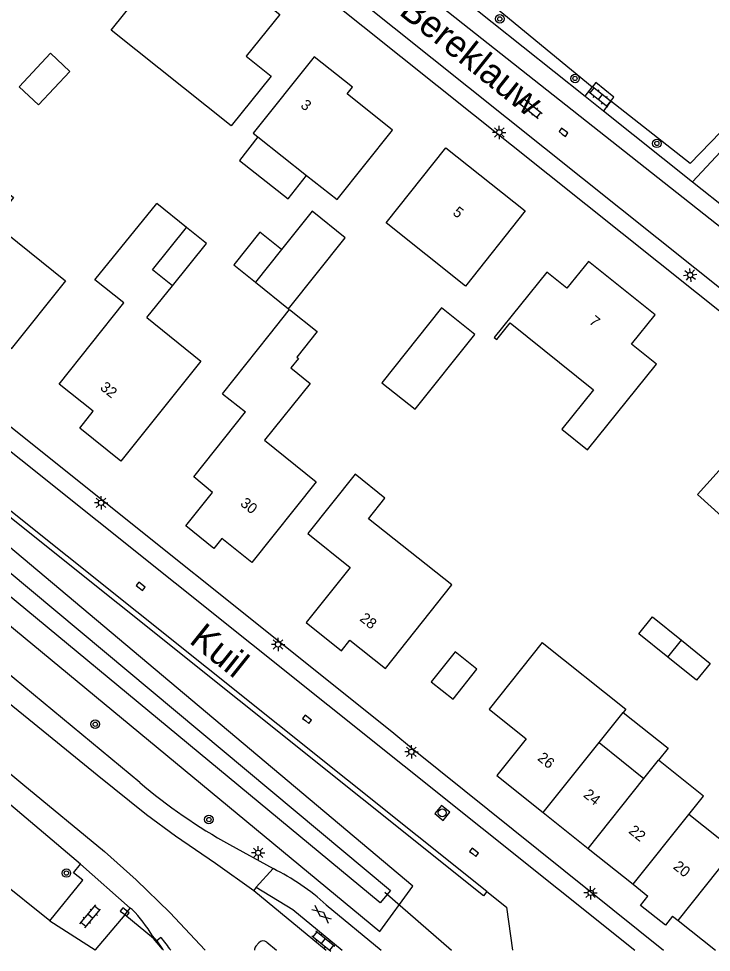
# Model space of a CAD drawing. Extents: x 136000 to 141014, y 402000 to 403500.
# Drawn here: x 137167.8 to 137232.8, y 401999.8 to 402087.3 of the extents above; entities that cross this region are included whole.
import ezdxf

# ---------------------------------------------------------------- set-up
doc = ezdxf.new("R2010")
doc.units = 0
for name, color, linetype in [('gg-anno-huisnummerreeks BGT', 7, 'Continuous'), ('gg-anno-openbare ruimte label', 7, 'Continuous'), ('gg-bbg-bijgebouw', 7, 'Continuous'), ('gg-bbg-gedigitaliseerde bebouwing', 7, 'Continuous'), ('gg-bbg-gedigitaliseerde bijgebouw', 7, 'Continuous'), ('gg-bbg-hoofdgebouw', 7, 'Continuous'), ('gg-bbg-luifel en loopbrug', 7, 'Continuous'), ('gg-bbg-tussenscheiding', 7, 'Continuous'), ('gg-knt-verharding', 7, 'Continuous'), ('gg-knt-verharding nz', 7, 'Continuous'), ('gg-kntw-bovenkant insteek waterloop', 7, 'Continuous'), ('gg-kntw-waterlijn', 7, 'Continuous'), ('gg-kwrk-duiker nz buis', 7, 'Continuous'), ('gt-grn-groengrens', 7, 'Continuous'), ('gt-grn-weggrens', 7, 'Continuous'), ('gt-symb-boom', 7, 'Continuous'), ('gt-symb-gesloten verharding', 7, 'Continuous'), ('gt-symb-klinker verharding', 7, 'Continuous'), ('gt-symb-kolk', 7, 'Continuous'), ('gt-symb-lichtmast', 7, 'Continuous'), ('gt-symb-rioolschacht', 7, 'Continuous')]:
    doc.layers.add(name, color=color, linetype=linetype)

# ---------------------------------------------------------------- blocks, each defined once
blk = doc.blocks.new('gt0-BOOM')
at = {"layer": 'gt-symb-boom'}
for radius in [0.4, 0.2]:
    blk.add_circle((0, 0), radius, dxfattribs=at)
blk = doc.blocks.new('gt0-KOLK')
at = {"layer": 'gt-symb-kolk'}
blk.add_lwpolyline([(0, 0), (0.375, 0), (0.375, 0.4), (-0.375, 0.4), (-0.375, 0), (0, 0)], dxfattribs=at)
blk = doc.blocks.new('gt0-LMAST')
at = {"layer": 'gt-symb-lichtmast'}
for p, q in [((-0.182, 0.173), (-0.447, 0.438)), ((-0.005, 0.246), (-0.005, 0.621)), ((0.172, 0.173), (0.437, 0.438)), ((-0.255, -0.004), (-0.63, -0.004)), ((-0.182, -0.181), (-0.447, -0.446)), ((-0.005, -0.254), (-0.005, -0.629)), ((0.437, -0.446), (0.172, -0.181)), ((0.245, -0.004), (0.62, -0.004))]:
    blk.add_line(p, q, dxfattribs=at)
blk.add_circle((-0.005, -0.004), 0.25, dxfattribs=at)
blk = doc.blocks.new('gt0-KL1')
at = {"layer": 'gt-symb-klinker verharding'}
for p, q in [((-1.15, 0.3), (1.15, 0.3)), ((-1, -0.3), (-1, 0.3)), ((-0.5, 0.3), (-0.5, 0.45)), ((0, -0.3), (0, 0.3)), ((0.5, 0.3), (0.5, 0.45)), ((1, -0.3), (1, 0.3)), ((-1.15, -0.3), (1.15, -0.3)), ((-0.5, -0.45), (-0.5, -0.3)), ((0.5, -0.45), (0.5, -0.3))]:
    blk.add_line(p, q, dxfattribs=at)
blk = doc.blocks.new('gt0-GESVH1')
at = {"layer": 'gt-symb-gesloten verharding'}
for p, q in [((-0.992, -0.261), (0.008, 0.239)), ((0.008, -0.261), (-0.992, 0.239)), ((0.008, 0.239), (1.008, -0.261)), ((1.008, 0.239), (0.008, -0.261))]:
    blk.add_line(p, q, dxfattribs=at)
blk = doc.blocks.new('gt0-RS')
at = {"layer": 'gt-symb-rioolschacht'}
blk.add_lwpolyline([(-0.5, -0.5), (0.5, -0.5), (0.5, 0.5), (-0.5, 0.5)], close=True, dxfattribs=at)
blk.add_circle((0, 0), 0.375, dxfattribs=at)

msp = doc.modelspace()

# ---------------------------------------------------------------- linework, layer by layer
at = {"layer": 'gg-bbg-bijgebouw'}
for points in [[(137193.142, 402060.138), (137198.47, 402066.8), (137195.35, 402069.29)], [(137210.63, 402057.74), (137207.5, 402060.24), (137201.89, 402053.21), (137205.01, 402050.72), (137210.63, 402057.74)]]:
    msp.add_lwpolyline(points, dxfattribs=at)
at = {"layer": 'gg-bbg-gedigitaliseerde bebouwing'}
for p, q in [((137183.596, 402067.758), (137180.79, 402070.02)), ((137179.85, 402059.31), (137182.259, 402062.297)), ((137186.96, 402052.18), (137191.33, 402057.66)), ((137222.269, 402019.477), (137224.534, 402022.3)), ((137222.269, 402019.477), (137226.474, 402016.113)), ((137226.474, 402016.113), (137227.848, 402017.832)), ((137234.901, 402009.371), (137230.69, 402012.74))]:
    msp.add_line(p, q, dxfattribs=at)
for points in [[(137182.259, 402062.297), (137180.4, 402063.795), (137183.596, 402067.758)], [(137191.33, 402057.66), (137193.242, 402060.058), (137195.83, 402057.995), (137193.924, 402055.605), (137194.08, 402055.48)], [(137194.08, 402055.48), (137193.369, 402054.598), (137195.183, 402053.134), (137190.887, 402047.806), (137195.73, 402043.9)], [(137238.45, 402050.46), (137231.492, 402042.741), (137236.657, 402038.085), (137235.581, 402036.891), (137238.621, 402034.15)], [(137216.94, 402028.85), (137224.766, 402022.589), (137224.534, 402022.3)], [(137230.69, 402012.74), (137232.064, 402014.458), (137227.848, 402017.832)]]:
    msp.add_lwpolyline(points, dxfattribs=at)
at = {"layer": 'gg-bbg-gedigitaliseerde bijgebouw'}
for p, q in [((137195.35, 402069.29), (137192.477, 402065.692)), ((137192.477, 402065.692), (137190.04, 402062.64)), ((137190.04, 402062.64), (137193.142, 402060.138))]:
    msp.add_line(p, q, dxfattribs=at)
for points in [[(137167.893, 402080.955), (137169.716, 402079.246), (137172.657, 402082.382), (137170.834, 402084.091), (137167.893, 402080.955)], [(137228.711, 402027.483), (137225.98, 402029.68), (137227.26, 402031.26), (137229.987, 402029.066)], [(137229.987, 402029.066), (137232.68, 402026.9), (137231.4, 402025.32), (137228.711, 402027.483)], [(137206.535, 402025.152), (137208.576, 402023.534), (137210.807, 402026.349), (137208.765, 402027.967), (137206.535, 402025.152)]]:
    msp.add_lwpolyline(points, dxfattribs=at)
at = {"layer": 'gg-bbg-hoofdgebouw'}
for p, q in [((137190.273, 402076.248), (137194.844, 402072.635)), ((137227.51, 402059.57), (137221.27, 402064.58)), ((137186.96, 402052.18), (137189.105, 402050.484)), ((137184.26, 402044.38), (137189.105, 402050.484)), ((137217.016, 402012.929), (137221.235, 402009.554)), ((137221.235, 402009.554), (137225.448, 402006.184)), ((137225.448, 402006.184), (137226.837, 402005.073)), ((137229.16, 402003.214), (137229.672, 402002.805)), ((137229.672, 402002.805), (137233.178, 402000))]:
    msp.add_line(p, q, dxfattribs=at)
for points in [[(137192.338, 402087.711), (137189.19, 402083.82), (137191.528, 402081.943), (137187.777, 402077.273), (137176.53, 402086.27), (137183.426, 402094.866), (137183.663, 402094.68), (137183.16, 402094.05), (137187.871, 402090.297), (137188.375, 402090.91), (137192.338, 402087.711)], [(137202.89, 402076.89), (137198.65, 402080.28), (137199.15, 402080.9), (137195.56, 402083.75), (137189.84, 402076.59), (137190.273, 402076.248)], [(137194.844, 402072.635), (137197.71, 402070.37), (137202.89, 402076.89)], [(137215.35, 402069.31), (137209.75, 402062.27), (137202.3, 402068.2), (137207.89, 402075.24), (137215.35, 402069.31)], [(137156.9, 402067.42), (137162.52, 402074.43), (137167.36, 402070.56), (137165.46, 402068.18), (137172.24, 402062.75), (137167.14, 402056.37), (137161.75, 402060.66), (137161.28, 402060.08), (137157.99, 402062.71), (137159.86, 402065.05), (137156.9, 402067.42)], [(137179.85, 402059.31), (137184.93, 402055.24), (137177.41, 402045.85), (137173.57, 402048.94), (137174.83, 402050.53), (137171.64, 402053.07), (137177.7, 402060.69), (137175, 402062.84), (137180.79, 402070.02)], [(137221.27, 402064.58), (137219.251, 402062.072), (137217.381, 402063.576), (137212.441, 402057.438), (137212.674, 402057.25), (137213.928, 402058.808), (137221.74, 402052.55)], [(137221.19, 402046.92), (137227.654, 402054.948), (137225.309, 402056.836), (137227.51, 402059.57)], [(137221.74, 402052.55), (137218.781, 402048.864), (137221.19, 402046.92)], [(137195.73, 402043.9), (137189.72, 402036.36), (137186.89, 402038.61), (137186.14, 402037.68), (137183.51, 402039.79), (137186.02, 402042.93), (137184.26, 402044.38)], [(137208.47, 402034.25), (137200.65, 402040.45), (137202.19, 402042.37), (137199.38, 402044.63), (137194.97, 402039.06), (137198.92, 402035.9), (137194.79, 402030.73), (137198.11, 402028.08), (137198.91, 402029.08), (137202.23, 402026.41), (137208.47, 402034.25)], [(137216.94, 402028.85), (137211.95, 402022.62), (137215.44, 402019.83), (137212.69, 402016.39), (137217.016, 402012.929)], [(137229.16, 402003.214), (137228.478, 402002.363), (137226.152, 402004.212), (137226.837, 402005.073)]]:
    msp.add_lwpolyline(points, dxfattribs=at)
at = {"layer": 'gg-bbg-luifel en loopbrug'}
for points in [[(137190.273, 402076.248), (137188.537, 402074.053), (137193.109, 402070.44), (137194.844, 402072.635)], [(137182.259, 402062.297), (137185.454, 402066.259), (137183.596, 402067.758)], [(137192.477, 402065.692), (137190.47, 402067.31), (137188.019, 402064.27), (137190.04, 402062.64)], [(137224.534, 402022.3), (137228.734, 402018.939), (137227.848, 402017.832)]]:
    msp.add_lwpolyline(points, dxfattribs=at)
at = {"layer": 'gg-bbg-tussenscheiding'}
for p, q in [((137228.711, 402027.483), (137229.987, 402029.066)), ((137217.016, 402012.929), (137222.269, 402019.477)), ((137221.235, 402009.554), (137226.474, 402016.113)), ((137225.448, 402006.184), (137230.69, 402012.74)), ((137229.672, 402002.805), (137234.901, 402009.371))]:
    msp.add_line(p, q, dxfattribs=at)
at = {"layer": 'gg-knt-verharding'}
for p, q in [((137236.54, 402057.51), (137171.536, 402109.464)), ((137209.154, 402089.482), (137220.95, 402080.082)), ((137220.95, 402080.082), (137221.622, 402080.926)), ((137220.95, 402080.082), (137222.691, 402078.695)), ((137223.367, 402079.603), (137222.691, 402078.695)), ((137222.691, 402078.695), (137231.03, 402072.049)), ((137231.03, 402072.049), (137234.48, 402069.3)), ((137211.745, 402005.497), (137131.617, 402069.523)), ((137151.833, 402061.255), (137202.83, 402020.5)), ((137173.632, 402008.079), (137152.407, 402025.931)), ((137202.83, 402020.5), (137204.87, 402018.83)), ((137204.87, 402018.83), (137228.293, 402000)), ((137187.613, 402009.908), (137191.694, 402007.66)), ((137173.632, 402008.079), (137178.314, 402003.964)), ((137170.781, 402002.759), (137173.858, 402006.561)), ((137190.106, 402005.908), (137189.883, 402005.597)), ((137189.883, 402005.597), (137196.662, 402000)), ((137177.784, 402003.334), (137178.314, 402003.964)), ((137178.488, 402003.813), (137178.314, 402003.964)), ((137196.689, 402004.269), (137201.83, 402000)), ((137177.784, 402003.334), (137175.005, 402000.028)), ((137180.797, 402000.877), (137180.389, 402001.366)), ((137181.175, 402001.209), (137180.797, 402000.877)), ((137180.797, 402000.877), (137181.329, 402000.109)), ((137190.071, 402000.373), (137190.355, 402000.709)), ((137191.101, 402000.759), (137192.013, 402000)), ((137181.329, 402000.109), (137181.412, 402000))]:
    msp.add_line(p, q, dxfattribs=at)
for points in [[(137223.367, 402079.603), (137223.653, 402079.987), (137221.962, 402081.353), (137221.622, 402080.926)], [(137179.195, 402015.74), (137160.136, 402031.481), (137145.396, 402043.745)], [(137173.858, 402006.561), (137172.988, 402007.276), (137173.632, 402008.079)], [(137190.106, 402005.908), (137193.554, 402003.826), (137198.185, 402000)], [(137211.745, 402005.497), (137213.58, 402004.03), (137214.134, 402000)], [(137181.329, 402000.109), (137180.49, 402001.11), (137177.784, 402003.334)]]:
    msp.add_lwpolyline(points, dxfattribs=at)
for centre, radius, start, end in [((137212.455, 402054.757), 51.27, 229.55393, 241.01755), ((137182.384, 401988.572), 21.237, 47.65651, 63.99999), ((137169.679, 401995.008), 12.455, 30.6968, 44.9883), ((137235.38, 402042.163), 67.937, 217.07266, 218.36166), ((137190.756, 402000.323), 0.556, 51.62693, 136.042), ((137190.496, 402000.029), 0.547, 141.01235, 183.04186)]:
    msp.add_arc(centre, radius, start, end, dxfattribs=at)
at = {"layer": 'gg-knt-verharding nz'}
for p, q in [((137236.866, 402059.445), (137172.601, 402110.823)), ((137233.87, 402067.6), (137200.33, 402094.097))]:
    msp.add_line(p, q, dxfattribs=at)
for points in [[(137131.54, 402080.04), (137132.06, 402074.74), (137225.63, 402000)], [(137135.643, 402050.535), (137137.269, 402049.025), (137140.426, 402045.678), (137142.949, 402043.119), (137147.571, 402039.235), (137152.198, 402035.472), (137165.929, 402023.993), (137170.646, 402020.175), (137175.214, 402016.442), (137179.822, 402012.719), (137182.537, 402010.735), (137186.306, 402008.166), (137189.883, 402005.597)], [(137130.8, 402044.838), (137137.823, 402040.555), (137140.656, 402038.468), (137145.261, 402034.744), (137149.884, 402030.921), (137154.544, 402027.028), (137163.674, 402019.341), (137168.249, 402015.588), (137175.879, 402009.25), (137178.851, 402006.612), (137182.006, 402003.541), (137185.316, 402000)]]:
    msp.add_lwpolyline(points, dxfattribs=at)
at = {"layer": 'gg-kntw-bovenkant insteek waterloop'}
msp.add_lwpolyline([(137129.55, 402069.25), (137125.76, 402064.53), (137201.72, 402001.76), (137204.81, 402006), (137129.55, 402069.25)], dxfattribs=at)
at = {"layer": 'gg-kntw-waterlijn'}
msp.add_lwpolyline([(137130.979, 402065.506), (137202.72, 402005.616), (137201.742, 402004.445), (137129.821, 402063.932), (137130.979, 402065.506)], dxfattribs=at)
at = {"layer": 'gg-kwrk-duiker nz buis'}
msp.add_line((137202.173, 402005.449), (137208.432, 402000), dxfattribs=at)
at = {"layer": 'gt-grn-groengrens'}
for p, q in [((137221.622, 402080.926), (137210.935, 402089.701)), ((137170.781, 402002.759), (137158.45, 402012.634)), ((137175.005, 402000.028), (137175.036, 402000))]:
    msp.add_line(p, q, dxfattribs=at)
for points in [[(137250.882, 402080.482), (137243.092, 402073.889), (137236.52, 402079.671), (137230.8, 402073.754), (137223.367, 402079.603)], [(137231.03, 402072.049), (137236.668, 402078.111), (137241.574, 402073.842)], [(137211.745, 402005.497), (137211.432, 402005.106), (137131.305, 402069.132), (137131.617, 402069.523)]]:
    msp.add_lwpolyline(points, dxfattribs=at)
at = {"layer": 'gt-grn-weggrens'}
for p, q in [((137190.106, 402005.908), (137191.694, 402007.66)), ((137170.781, 402002.759), (137175.005, 402000.028))]:
    msp.add_line(p, q, dxfattribs=at)

# ---------------------------------------------------------------- block references
at = {"layer": 'gt-symb-boom'}
for p in [(137212.957, 402087.31), (137220.009, 402081.733), (137227.683, 402075.643), (137175.022, 402021.19), (137185.68, 402012.253), (137172.319, 402007.24)]:
    msp.add_blockref('gt0-BOOM', p, dxfattribs=at)
at = {"layer": 'gt-symb-gesloten verharding', "rotation": -39.563508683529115}
msp.add_blockref('gt0-GESVH1', (137196.261, 402003.391), dxfattribs=at)
at = {"layer": 'gt-symb-klinker verharding'}
for p, rotation in [((137222.363, 402079.986), 141.45653728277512), ((137215.849, 402078.942), -38.62400399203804), ((137174.558, 402003.181), 50.11369967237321), ((137196.419, 402000.88), -38.704570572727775)]:
    msp.add_blockref('gt0-KL1', p, dxfattribs=dict(at, rotation=rotation))
at = {"layer": 'gt-symb-kolk'}
for p, rotation in [((137218.808, 402076.521), -36.663592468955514), ((137179.155, 402033.977), -38.704570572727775), ((137194.764, 402021.499), -38.704570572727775), ((137210.413, 402009.031), -38.704570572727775), ((137177.66, 402003.438), -39.11608916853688)]:
    msp.add_blockref('gt0-KOLK', p, dxfattribs=dict(at, rotation=rotation))
at = {"layer": 'gt-symb-lichtmast'}
for p in [(137212.915, 402076.676), (137175.57, 402041.952), (137192.165, 402028.679), (137204.671, 402018.605), (137190.307, 402009.144), (137221.475, 402005.393)]:
    msp.add_blockref('gt0-LMAST', p, dxfattribs=at)
at = {"layer": 'gt-symb-lichtmast', "rotation": 141.25072308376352}
msp.add_blockref('gt0-LMAST', (137230.801, 402063.301), dxfattribs=at)
at = {"layer": 'gt-symb-rioolschacht', "rotation": -38.704570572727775}
msp.add_blockref('gt0-RS', (137207.558, 402012.886), dxfattribs=at)

# ---------------------------------------------------------------- texts
at = {"layer": 'gg-anno-huisnummerreeks BGT'}
for s, rotation, p in [('3', 321.5, (137194.206, 402079.079)), ('5', 321.5, (137208.47, 402069.03)), ('7', 321.3, (137221.256, 402058.82)), ('32', 321.5, (137175.406, 402052.627)), ('30', 321.5, (137188.554, 402041.759)), ('28', 321.5, (137199.75, 402030.966)), ('26', 321.3, (137216.42, 402017.89)), ('24', 321.3, (137220.721, 402014.449)), ('22', 321.3, (137224.962, 402011.057)), ('20', 321.3, (137229.141, 402007.714))]:
    msp.add_text(s, height=1, rotation=rotation, dxfattribs=at).set_placement(p)
at = {"layer": 'gg-anno-openbare ruimte label'}
for s, p in [('Bereklauw', (137203.418, 402087.796)), ('Kuil', (137183.736, 402028.888))]:
    msp.add_text(s, height=2.5, rotation=321.4, dxfattribs=at).set_placement(p)

doc.saveas('drawing.dxf')
